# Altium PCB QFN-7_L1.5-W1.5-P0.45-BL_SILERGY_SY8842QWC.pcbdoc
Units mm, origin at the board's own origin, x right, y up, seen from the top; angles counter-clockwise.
Board outline 14.86 x 14.69 mm, 2 copper layers (Top Layer, Bottom Layer), stack 0 mm thick; 1 components, 0 nets, 7 pads, 0 vias.
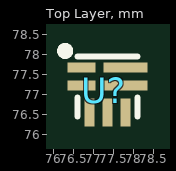
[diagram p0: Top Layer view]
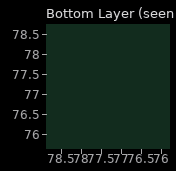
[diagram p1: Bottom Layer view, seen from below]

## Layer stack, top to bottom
Top Layer: signal copper (thickness not stored)
Bottom Layer: signal copper (thickness not stored)

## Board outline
84.71,69.85 69.85,69.85 69.85,84.54 84.71,84.54

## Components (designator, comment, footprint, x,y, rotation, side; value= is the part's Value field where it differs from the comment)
U? "" QFN-7_L1.5-W1.5-P0.45-BL_SILERGY_SY8842QWC 77.26,77.113 r0 top

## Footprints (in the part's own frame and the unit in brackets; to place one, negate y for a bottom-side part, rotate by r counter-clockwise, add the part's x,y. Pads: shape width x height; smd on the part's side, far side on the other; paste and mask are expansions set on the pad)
QFN-7_L1.5-W1.5-P0.45-BL_SILERGY_SY8842QWC [mm]
  rect 0.7x0.25 smd paste+0 mask+0.05: 1(-0.55,0.563) 2(-0.55,0.113)
  rect 0.25x0.7 smd paste+0 mask+0.05: 3(-0.35,-0.563) 4(0.1,-0.563) 5(0.55,-0.563)
  rect 1.1x0.25 smd paste+0 mask+0.05: 6(0.55,0.113) 7(0.55,0.563)
  silkscreen extent -1.06,-0.66 0.85,1.08

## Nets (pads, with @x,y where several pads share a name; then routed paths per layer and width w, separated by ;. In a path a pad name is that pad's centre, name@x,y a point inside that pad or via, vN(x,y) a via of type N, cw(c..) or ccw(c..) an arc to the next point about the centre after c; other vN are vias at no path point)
pads on no net: U?.1 U?.2 U?.3 U?.4 U?.5 U?.6 U?.7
